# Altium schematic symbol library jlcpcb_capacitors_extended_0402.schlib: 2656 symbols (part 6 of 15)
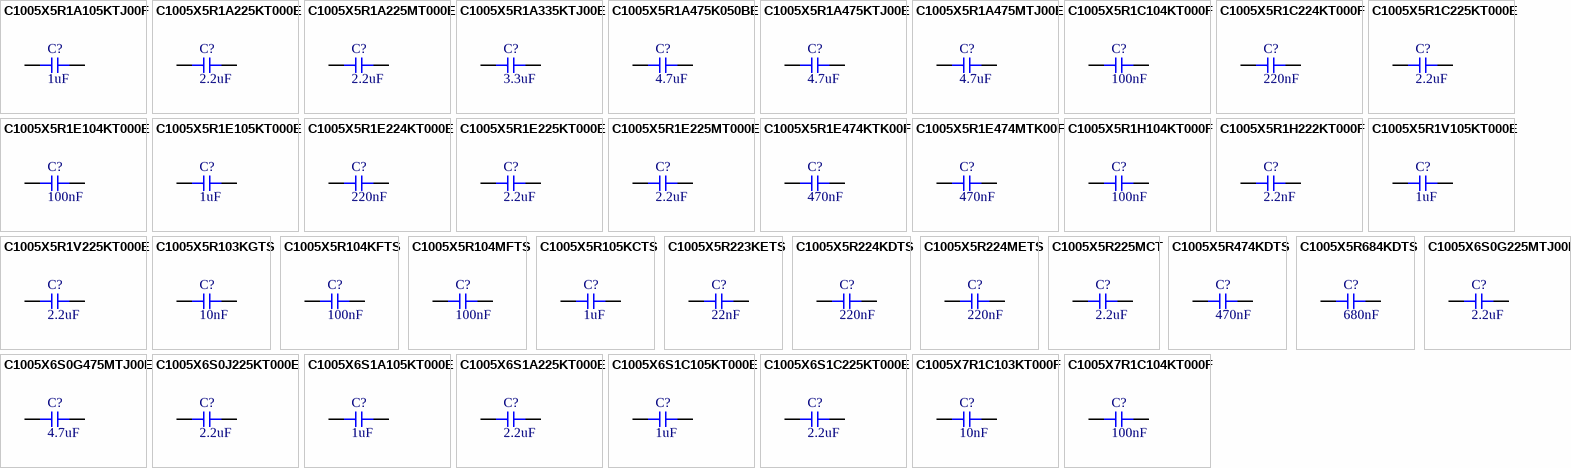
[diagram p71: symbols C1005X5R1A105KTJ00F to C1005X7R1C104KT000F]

## C1005X5R224KDTS
designator C?  Capacitance: 220nF  (hidden comment: *)
Capacitor, Ceramic (MLCC), 220nF, ±10%, 10V, X5R, ±10%, SMD 0402; Manufacturer: Darfon Elec; Manufacturer Part Number: C1005X5R224KDTS
footprint CAP-0402 (0402 (1005M) Capacitor)
pins: 1, 2

## C1005X5R224METS
designator C?  Capacitance: 220nF  (hidden comment: *)
Capacitor, Ceramic (MLCC), 220nF, ±20%, 16V, X5R, ±20%, SMD 0402; Manufacturer: Darfon Elec; Manufacturer Part Number: C1005X5R224METS
footprint CAP-0402 (0402 (1005M) Capacitor)
pins: 1, 2

## C1005X5R225MCT
designator C?  Capacitance: 2.2uF  (hidden comment: *)
Capacitor, Ceramic (MLCC), 2.2uF, ±20%, 6.3V, X5R, ±20%, SMD 0402; Manufacturer: Darfon Elec; Manufacturer Part Number: C1005X5R225MCT
footprint CAP-0402 (0402 (1005M) Capacitor)
pins: 1, 2

## C1005X5R474KDTS
designator C?  Capacitance: 470nF  (hidden comment: *)
Capacitor, Ceramic (MLCC), 470nF, ±10%, 10V, X5R, ±10%, SMD 0402; Manufacturer: Darfon Elec; Manufacturer Part Number: C1005X5R474KDTS
footprint CAP-0402 (0402 (1005M) Capacitor)
pins: 1, 2

## C1005X5R684KDTS
designator C?  Capacitance: 680nF  (hidden comment: *)
Capacitor, Ceramic (MLCC), 680nF, ±10%, 10V, X5R, ±10%, SMD 0402; Manufacturer: Darfon Elec; Manufacturer Part Number: C1005X5R684KDTS
footprint CAP-0402 (0402 (1005M) Capacitor)
pins: 1, 2

## C1005X6S0G225MTJ00F
designator C?  Capacitance: 2.2uF  (hidden comment: *)
Capacitor, Ceramic (MLCC), 2.2uF, ±20%, 4V, X6S, ±20%, SMD 0402; Manufacturer: TDK; Manufacturer Part Number: C1005X6S0G225MTJ00F
footprint CAP-0402 (0402 (1005M) Capacitor)
pins: 1, 2

## C1005X6S0G475MTJ00E
designator C?  Capacitance: 4.7uF  (hidden comment: *)
Capacitor, Ceramic (MLCC), 4.7uF, ±20%, 4V, X6S, ±20%, SMD 0402; Manufacturer: TDK; Manufacturer Part Number: C1005X6S0G475MTJ00E
footprint CAP-0402 (0402 (1005M) Capacitor)
pins: 1, 2

## C1005X6S0J225KT000E
designator C?  Capacitance: 2.2uF  (hidden comment: *)
Capacitor, Ceramic (MLCC), 2.2uF, ±10%, 6.3V, X6S, ±10%, SMD 0402; Manufacturer: TDK; Manufacturer Part Number: C1005X6S0J225KT000E
footprint CAP-0402 (0402 (1005M) Capacitor)
pins: 1, 2

## C1005X6S1A105KT000E
designator C?  Capacitance: 1uF  (hidden comment: *)
Capacitor, Ceramic (MLCC), 1uF, ±10%, 10V, X6S, ±10%, SMD 0402; Manufacturer: TDK; Manufacturer Part Number: C1005X6S1A105KT000E
footprint CAP-0402 (0402 (1005M) Capacitor)
pins: 1, 2

## C1005X6S1A225KT000E
designator C?  Capacitance: 2.2uF  (hidden comment: *)
Capacitor, Ceramic (MLCC), 2.2uF, ±10%, 10V, X6S, ±10%, SMD 0402; Manufacturer: TDK; Manufacturer Part Number: C1005X6S1A225KT000E
footprint CAP-0402 (0402 (1005M) Capacitor)
pins: 1, 2

## C1005X6S1C105KT000E
designator C?  Capacitance: 1uF  (hidden comment: *)
Capacitor, Ceramic (MLCC), 1uF, ±10%, 16V, X6S, ±10%, SMD 0402; Manufacturer: TDK; Manufacturer Part Number: C1005X6S1C105KT000E
footprint CAP-0402 (0402 (1005M) Capacitor)
pins: 1, 2

## C1005X6S1C225KT000E
designator C?  Capacitance: 2.2uF  (hidden comment: *)
Capacitor, Ceramic (MLCC), 2.2uF, ±10%, 16V, X6S, ±10%, SMD 0402; Manufacturer: TDK; Manufacturer Part Number: C1005X6S1C225KT000E
footprint CAP-0402 (0402 (1005M) Capacitor)
pins: 1, 2

## C1005X7R1C103KT000F
designator C?  Capacitance: 10nF  (hidden comment: *)
Capacitor, Ceramic (MLCC), 10nF, ±10%, 16V, X7R, ±10%, SMD 0402; Manufacturer: TDK; Manufacturer Part Number: C1005X7R1C103KT000F
footprint CAP-0402 (0402 (1005M) Capacitor)
pins: 1, 2

## C1005X7R1C104KT000F
designator C?  Capacitance: 100nF  (hidden comment: *)
Capacitor, Ceramic (MLCC), 100nF, ±10%, 16V, X7R, ±10%, SMD 0402; Manufacturer: TDK; Manufacturer Part Number: C1005X7R1C104KT000F
footprint CAP-0402 (0402 (1005M) Capacitor)
pins: 1, 2

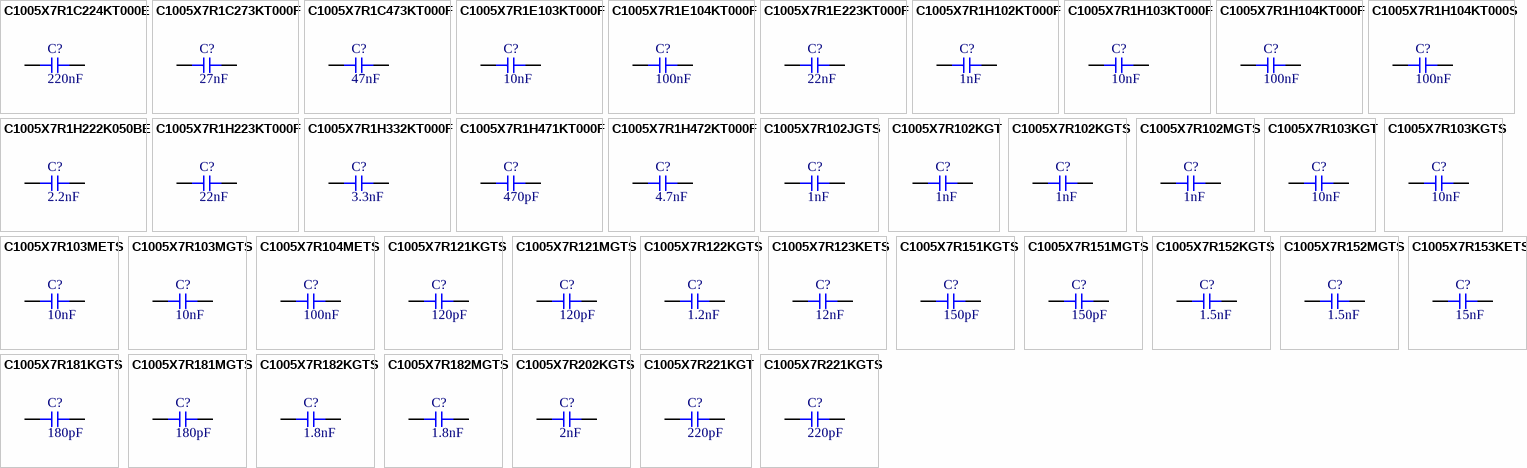
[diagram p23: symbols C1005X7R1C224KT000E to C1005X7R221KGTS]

## C1005X7R1C224KT000E
designator C?  Capacitance: 220nF  (hidden comment: *)
Capacitor, Ceramic (MLCC), 220nF, ±10%, 16V, X7R, ±10%, SMD 0402; Manufacturer: TDK; Manufacturer Part Number: C1005X7R1C224KT000E
footprint CAP-0402 (0402 (1005M) Capacitor)
pins: 1, 2

## C1005X7R1C273KT000F
designator C?  Capacitance: 27nF  (hidden comment: *)
Capacitor, Ceramic (MLCC), 27nF, ±10%, 16V, X7R, ±10%, SMD 0402; Manufacturer: TDK; Manufacturer Part Number: C1005X7R1C273KT000F
footprint CAP-0402 (0402 (1005M) Capacitor)
pins: 1, 2

## C1005X7R1C473KT000F
designator C?  Capacitance: 47nF  (hidden comment: *)
Capacitor, Ceramic (MLCC), 47nF, ±10%, 16V, X7R, ±10%, SMD 0402; Manufacturer: TDK; Manufacturer Part Number: C1005X7R1C473KT000F
footprint CAP-0402 (0402 (1005M) Capacitor)
pins: 1, 2

## C1005X7R1E103KT000F
designator C?  Capacitance: 10nF  (hidden comment: *)
Capacitor, Ceramic (MLCC), 10nF, ±10%, 25V, X7R, ±10%, SMD 0402; Manufacturer: TDK; Manufacturer Part Number: C1005X7R1E103KT000F
footprint CAP-0402 (0402 (1005M) Capacitor)
pins: 1, 2

## C1005X7R1E104KT000F
designator C?  Capacitance: 100nF  (hidden comment: *)
Capacitor, Ceramic (MLCC), 100nF, ±10%, 25V, X7R, ±10%, SMD 0402; Manufacturer: TDK; Manufacturer Part Number: C1005X7R1E104KT000F
footprint CAP-0402 (0402 (1005M) Capacitor)
pins: 1, 2

## C1005X7R1E223KT000F
designator C?  Capacitance: 22nF  (hidden comment: *)
Capacitor, Ceramic (MLCC), 22nF, ±10%, 25V, X7R, ±10%, SMD 0402; Manufacturer: TDK; Manufacturer Part Number: C1005X7R1E223KT000F
footprint CAP-0402 (0402 (1005M) Capacitor)
pins: 1, 2

## C1005X7R1H102KT000F
designator C?  Capacitance: 1nF  (hidden comment: *)
Capacitor, Ceramic (MLCC), 1nF, ±10%, 50V, X7R, ±10%, SMD 0402; Manufacturer: TDK; Manufacturer Part Number: C1005X7R1H102KT000F
footprint CAP-0402 (0402 (1005M) Capacitor)
pins: 1, 2

## C1005X7R1H103KT000F
designator C?  Capacitance: 10nF  (hidden comment: *)
Capacitor, Ceramic (MLCC), 10nF, ±10%, 50V, X7R, ±10%, SMD 0402; Manufacturer: TDK; Manufacturer Part Number: C1005X7R1H103KT000F
footprint CAP-0402 (0402 (1005M) Capacitor)
pins: 1, 2

## C1005X7R1H104KT000F
designator C?  Capacitance: 100nF  (hidden comment: *)
Capacitor, Ceramic (MLCC), 100nF, ±10%, 50V, X7R, ±10%, SMD 0402; Manufacturer: TDK; Manufacturer Part Number: C1005X7R1H104KT000F
footprint CAP-0402 (0402 (1005M) Capacitor)
pins: 1, 2

## C1005X7R1H104KT000S
designator C?  Capacitance: 100nF  (hidden comment: *)
Capacitor, Ceramic (MLCC), 100nF, ±10%, 50V, X7R, ±10%, SMD 0402; Manufacturer: TDK; Manufacturer Part Number: C1005X7R1H104KT000S
footprint CAP-0402 (0402 (1005M) Capacitor)
pins: 1, 2

## C1005X7R1H222K050BE
designator C?  Capacitance: 2.2nF  (hidden comment: *)
Capacitor, Ceramic (MLCC), 2.2nF, ±10%, 50V, X7R, ±10%, SMD 0402; Manufacturer: TDK; Manufacturer Part Number: C1005X7R1H222K050BE
footprint CAP-0402 (0402 (1005M) Capacitor)
pins: 1, 2

## C1005X7R1H223KT000F
designator C?  Capacitance: 22nF  (hidden comment: *)
Capacitor, Ceramic (MLCC), 22nF, ±10%, 50V, X7R, ±10%, SMD 0402; Manufacturer: TDK; Manufacturer Part Number: C1005X7R1H223KT000F
footprint CAP-0402 (0402 (1005M) Capacitor)
pins: 1, 2

## C1005X7R1H332KT000F
designator C?  Capacitance: 3.3nF  (hidden comment: *)
Capacitor, Ceramic (MLCC), 3.3nF, ±10%, 50V, X7R, ±10%, SMD 0402; Manufacturer: TDK; Manufacturer Part Number: C1005X7R1H332KT000F
footprint CAP-0402 (0402 (1005M) Capacitor)
pins: 1, 2

## C1005X7R1H471KT000F
designator C?  Capacitance: 470pF  (hidden comment: *)
Capacitor, Ceramic (MLCC), 470pF, ±10%, 50V, X7R, ±10%, SMD 0402; Manufacturer: TDK; Manufacturer Part Number: C1005X7R1H471KT000F
footprint CAP-0402 (0402 (1005M) Capacitor)
pins: 1, 2

## C1005X7R1H472KT000F
designator C?  Capacitance: 4.7nF  (hidden comment: *)
Capacitor, Ceramic (MLCC), 4.7nF, ±10%, 50V, X7R, ±10%, SMD 0402; Manufacturer: TDK; Manufacturer Part Number: C1005X7R1H472KT000F
footprint CAP-0402 (0402 (1005M) Capacitor)
pins: 1, 2

## C1005X7R102JGTS
designator C?  Capacitance: 1nF  (hidden comment: *)
Capacitor, Ceramic (MLCC), 1nF, ±5%, 50V, X7R, ±5%, SMD 0402; Manufacturer: Darfon Elec; Manufacturer Part Number: C1005X7R102JGTS
footprint CAP-0402 (0402 (1005M) Capacitor)
pins: 1, 2

## C1005X7R102KGT
designator C?  Capacitance: 1nF  (hidden comment: *)
Capacitor, Ceramic (MLCC), 1nF, ±10%, 50V, X7R, ±10%, SMD 0402; Manufacturer: Darfon Elec; Manufacturer Part Number: C1005X7R102KGT
footprint CAP-0402 (0402 (1005M) Capacitor)
pins: 1, 2

## C1005X7R102KGTS
designator C?  Capacitance: 1nF  (hidden comment: *)
Capacitor, Ceramic (MLCC), 1nF, ±10%, 50V, X7R, ±10%, SMD 0402; Manufacturer: Darfon Elec; Manufacturer Part Number: C1005X7R102KGTS
footprint CAP-0402 (0402 (1005M) Capacitor)
pins: 1, 2

## C1005X7R102MGTS
designator C?  Capacitance: 1nF  (hidden comment: *)
Capacitor, Ceramic (MLCC), 1nF, ±20%, 50V, X7R, ±20%, SMD 0402; Manufacturer: Darfon Elec; Manufacturer Part Number: C1005X7R102MGTS
footprint CAP-0402 (0402 (1005M) Capacitor)
pins: 1, 2

## C1005X7R103KGT
designator C?  Capacitance: 10nF  (hidden comment: *)
Capacitor, Ceramic (MLCC), 10nF, ±10%, 50V, X7R, ±10%, SMD 0402; Manufacturer: Darfon Elec; Manufacturer Part Number: C1005X7R103KGT
footprint CAP-0402 (0402 (1005M) Capacitor)
pins: 1, 2

## C1005X7R103KGTS
designator C?  Capacitance: 10nF  (hidden comment: *)
Capacitor, Ceramic (MLCC), 10nF, ±10%, 50V, X7R, ±10%, SMD 0402; Manufacturer: Darfon Elec; Manufacturer Part Number: C1005X7R103KGTS
footprint CAP-0402 (0402 (1005M) Capacitor)
pins: 1, 2

## C1005X7R103METS
designator C?  Capacitance: 10nF  (hidden comment: *)
Capacitor, Ceramic (MLCC), 10nF, ±20%, 16V, X7R, ±20%, SMD 0402; Manufacturer: Darfon Elec; Manufacturer Part Number: C1005X7R103METS
footprint CAP-0402 (0402 (1005M) Capacitor)
pins: 1, 2

## C1005X7R103MGTS
designator C?  Capacitance: 10nF  (hidden comment: *)
Capacitor, Ceramic (MLCC), 10nF, ±20%, 50V, X7R, ±20%, SMD 0402; Manufacturer: Darfon Elec; Manufacturer Part Number: C1005X7R103MGTS
footprint CAP-0402 (0402 (1005M) Capacitor)
pins: 1, 2

## C1005X7R104METS
designator C?  Capacitance: 100nF  (hidden comment: *)
Capacitor, Ceramic (MLCC), 100nF, ±20%, 16V, X7R, ±20%, SMD 0402; Manufacturer: Darfon Elec; Manufacturer Part Number: C1005X7R104METS
footprint CAP-0402 (0402 (1005M) Capacitor)
pins: 1, 2

## C1005X7R121KGTS
designator C?  Capacitance: 120pF  (hidden comment: *)
Capacitor, Ceramic (MLCC), 120pF, ±10%, 50V, X7R, ±10%, SMD 0402; Manufacturer: Darfon Elec; Manufacturer Part Number: C1005X7R121KGTS
footprint CAP-0402 (0402 (1005M) Capacitor)
pins: 1, 2

## C1005X7R121MGTS
designator C?  Capacitance: 120pF  (hidden comment: *)
Capacitor, Ceramic (MLCC), 120pF, ±20%, 50V, X7R, ±20%, SMD 0402; Manufacturer: Darfon Elec; Manufacturer Part Number: C1005X7R121MGTS
footprint CAP-0402 (0402 (1005M) Capacitor)
pins: 1, 2

## C1005X7R122KGTS
designator C?  Capacitance: 1.2nF  (hidden comment: *)
Capacitor, Ceramic (MLCC), 1.2nF, ±10%, 50V, X7R, ±10%, SMD 0402; Manufacturer: Darfon Elec; Manufacturer Part Number: C1005X7R122KGTS
footprint CAP-0402 (0402 (1005M) Capacitor)
pins: 1, 2

## C1005X7R123KETS
designator C?  Capacitance: 12nF  (hidden comment: *)
Capacitor, Ceramic (MLCC), 12nF, ±10%, 16V, X7R, ±10%, SMD 0402; Manufacturer: Darfon Elec; Manufacturer Part Number: C1005X7R123KETS
footprint CAP-0402 (0402 (1005M) Capacitor)
pins: 1, 2

## C1005X7R151KGTS
designator C?  Capacitance: 150pF  (hidden comment: *)
Capacitor, Ceramic (MLCC), 150pF, ±10%, 50V, X7R, ±10%, SMD 0402; Manufacturer: Darfon Elec; Manufacturer Part Number: C1005X7R151KGTS
footprint CAP-0402 (0402 (1005M) Capacitor)
pins: 1, 2

## C1005X7R151MGTS
designator C?  Capacitance: 150pF  (hidden comment: *)
Capacitor, Ceramic (MLCC), 150pF, ±20%, 50V, X7R, ±20%, SMD 0402; Manufacturer: Darfon Elec; Manufacturer Part Number: C1005X7R151MGTS
footprint CAP-0402 (0402 (1005M) Capacitor)
pins: 1, 2

## C1005X7R152KGTS
designator C?  Capacitance: 1.5nF  (hidden comment: *)
Capacitor, Ceramic (MLCC), 1.5nF, ±10%, 50V, X7R, ±10%, SMD 0402; Manufacturer: Darfon Elec; Manufacturer Part Number: C1005X7R152KGTS
footprint CAP-0402 (0402 (1005M) Capacitor)
pins: 1, 2

## C1005X7R152MGTS
designator C?  Capacitance: 1.5nF  (hidden comment: *)
Capacitor, Ceramic (MLCC), 1.5nF, ±20%, 50V, X7R, ±20%, SMD 0402; Manufacturer: Darfon Elec; Manufacturer Part Number: C1005X7R152MGTS
footprint CAP-0402 (0402 (1005M) Capacitor)
pins: 1, 2

## C1005X7R153KETS
designator C?  Capacitance: 15nF  (hidden comment: *)
Capacitor, Ceramic (MLCC), 15nF, ±10%, 16V, X7R, ±10%, SMD 0402; Manufacturer: Darfon Elec; Manufacturer Part Number: C1005X7R153KETS
footprint CAP-0402 (0402 (1005M) Capacitor)
pins: 1, 2

## C1005X7R181KGTS
designator C?  Capacitance: 180pF  (hidden comment: *)
Capacitor, Ceramic (MLCC), 180pF, ±10%, 50V, X7R, ±10%, SMD 0402; Manufacturer: Darfon Elec; Manufacturer Part Number: C1005X7R181KGTS
footprint CAP-0402 (0402 (1005M) Capacitor)
pins: 1, 2

## C1005X7R181MGTS
designator C?  Capacitance: 180pF  (hidden comment: *)
Capacitor, Ceramic (MLCC), 180pF, ±20%, 50V, X7R, ±20%, SMD 0402; Manufacturer: Darfon Elec; Manufacturer Part Number: C1005X7R181MGTS
footprint CAP-0402 (0402 (1005M) Capacitor)
pins: 1, 2

## C1005X7R182KGTS
designator C?  Capacitance: 1.8nF  (hidden comment: *)
Capacitor, Ceramic (MLCC), 1.8nF, ±10%, 50V, X7R, ±10%, SMD 0402; Manufacturer: Darfon Elec; Manufacturer Part Number: C1005X7R182KGTS
footprint CAP-0402 (0402 (1005M) Capacitor)
pins: 1, 2

## C1005X7R182MGTS
designator C?  Capacitance: 1.8nF  (hidden comment: *)
Capacitor, Ceramic (MLCC), 1.8nF, ±20%, 50V, X7R, ±20%, SMD 0402; Manufacturer: Darfon Elec; Manufacturer Part Number: C1005X7R182MGTS
footprint CAP-0402 (0402 (1005M) Capacitor)
pins: 1, 2

## C1005X7R202KGTS
designator C?  Capacitance: 2nF  (hidden comment: *)
Capacitor, Ceramic (MLCC), 2nF, ±10%, 50V, X7R, ±10%, SMD 0402; Manufacturer: Darfon Elec; Manufacturer Part Number: C1005X7R202KGTS
footprint CAP-0402 (0402 (1005M) Capacitor)
pins: 1, 2

## C1005X7R221KGT
designator C?  Capacitance: 220pF  (hidden comment: *)
Capacitor, Ceramic (MLCC), 220pF, ±10%, 50V, X7R, ±10%, SMD 0402; Manufacturer: Darfon Elec; Manufacturer Part Number: C1005X7R221KGT
footprint CAP-0402 (0402 (1005M) Capacitor)
pins: 1, 2

## C1005X7R221KGTS
designator C?  Capacitance: 220pF  (hidden comment: *)
Capacitor, Ceramic (MLCC), 220pF, ±10%, 50V, X7R, ±10%, SMD 0402; Manufacturer: Darfon Elec; Manufacturer Part Number: C1005X7R221KGTS
footprint CAP-0402 (0402 (1005M) Capacitor)
pins: 1, 2

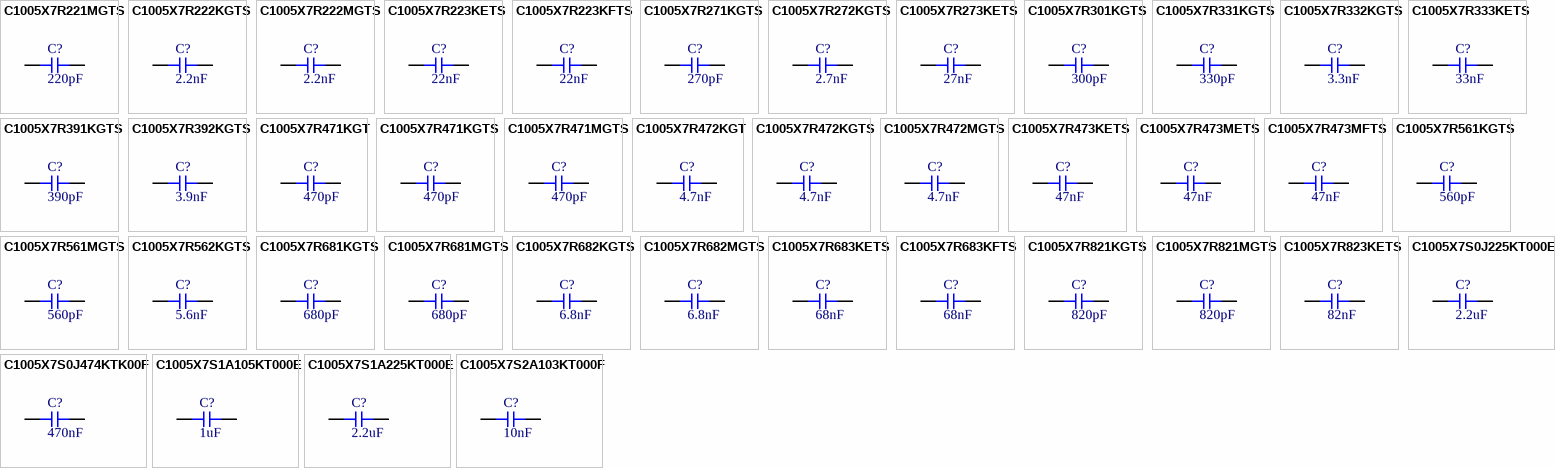
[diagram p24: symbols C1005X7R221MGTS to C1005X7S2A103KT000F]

## C1005X7R221MGTS
designator C?  Capacitance: 220pF  (hidden comment: *)
Capacitor, Ceramic (MLCC), 220pF, ±20%, 50V, X7R, ±20%, SMD 0402; Manufacturer: Darfon Elec; Manufacturer Part Number: C1005X7R221MGTS
footprint CAP-0402 (0402 (1005M) Capacitor)
pins: 1, 2

## C1005X7R222KGTS
designator C?  Capacitance: 2.2nF  (hidden comment: *)
Capacitor, Ceramic (MLCC), 2.2nF, ±10%, 50V, X7R, ±10%, SMD 0402; Manufacturer: Darfon Elec; Manufacturer Part Number: C1005X7R222KGTS
footprint CAP-0402 (0402 (1005M) Capacitor)
pins: 1, 2

## C1005X7R222MGTS
designator C?  Capacitance: 2.2nF  (hidden comment: *)
Capacitor, Ceramic (MLCC), 2.2nF, ±20%, 50V, X7R, ±20%, SMD 0402; Manufacturer: Darfon Elec; Manufacturer Part Number: C1005X7R222MGTS
footprint CAP-0402 (0402 (1005M) Capacitor)
pins: 1, 2

## C1005X7R223KETS
designator C?  Capacitance: 22nF  (hidden comment: *)
Capacitor, Ceramic (MLCC), 22nF, ±10%, 16V, X7R, ±10%, SMD 0402; Manufacturer: Darfon Elec; Manufacturer Part Number: C1005X7R223KETS
footprint CAP-0402 (0402 (1005M) Capacitor)
pins: 1, 2

## C1005X7R223KFTS
designator C?  Capacitance: 22nF  (hidden comment: *)
Capacitor, Ceramic (MLCC), 22nF, ±10%, 25V, X7R, ±10%, SMD 0402; Manufacturer: Darfon Elec; Manufacturer Part Number: C1005X7R223KFTS
footprint CAP-0402 (0402 (1005M) Capacitor)
pins: 1, 2

## C1005X7R271KGTS
designator C?  Capacitance: 270pF  (hidden comment: *)
Capacitor, Ceramic (MLCC), 270pF, ±10%, 50V, X7R, ±10%, SMD 0402; Manufacturer: Darfon Elec; Manufacturer Part Number: C1005X7R271KGTS
footprint CAP-0402 (0402 (1005M) Capacitor)
pins: 1, 2

## C1005X7R272KGTS
designator C?  Capacitance: 2.7nF  (hidden comment: *)
Capacitor, Ceramic (MLCC), 2.7nF, ±10%, 50V, X7R, ±10%, SMD 0402; Manufacturer: Darfon Elec; Manufacturer Part Number: C1005X7R272KGTS
footprint CAP-0402 (0402 (1005M) Capacitor)
pins: 1, 2

## C1005X7R273KETS
designator C?  Capacitance: 27nF  (hidden comment: *)
Capacitor, Ceramic (MLCC), 27nF, ±10%, 16V, X7R, ±10%, SMD 0402; Manufacturer: Darfon Elec; Manufacturer Part Number: C1005X7R273KETS
footprint CAP-0402 (0402 (1005M) Capacitor)
pins: 1, 2

## C1005X7R301KGTS
designator C?  Capacitance: 300pF  (hidden comment: *)
Capacitor, Ceramic (MLCC), 300pF, ±10%, 50V, X7R, ±10%, SMD 0402; Manufacturer: Darfon Elec; Manufacturer Part Number: C1005X7R301KGTS
footprint CAP-0402 (0402 (1005M) Capacitor)
pins: 1, 2

## C1005X7R331KGTS
designator C?  Capacitance: 330pF  (hidden comment: *)
Capacitor, Ceramic (MLCC), 330pF, ±10%, 50V, X7R, ±10%, SMD 0402; Manufacturer: Darfon Elec; Manufacturer Part Number: C1005X7R331KGTS
footprint CAP-0402 (0402 (1005M) Capacitor)
pins: 1, 2

## C1005X7R332KGTS
designator C?  Capacitance: 3.3nF  (hidden comment: *)
Capacitor, Ceramic (MLCC), 3.3nF, ±10%, 50V, X7R, ±10%, SMD 0402; Manufacturer: Darfon Elec; Manufacturer Part Number: C1005X7R332KGTS
footprint CAP-0402 (0402 (1005M) Capacitor)
pins: 1, 2

## C1005X7R333KETS
designator C?  Capacitance: 33nF  (hidden comment: *)
Capacitor, Ceramic (MLCC), 33nF, ±10%, 16V, X7R, ±10%, SMD 0402; Manufacturer: Darfon Elec; Manufacturer Part Number: C1005X7R333KETS
footprint CAP-0402 (0402 (1005M) Capacitor)
pins: 1, 2

## C1005X7R391KGTS
designator C?  Capacitance: 390pF  (hidden comment: *)
Capacitor, Ceramic (MLCC), 390pF, ±10%, 50V, X7R, ±10%, SMD 0402; Manufacturer: Darfon Elec; Manufacturer Part Number: C1005X7R391KGTS
footprint CAP-0402 (0402 (1005M) Capacitor)
pins: 1, 2

## C1005X7R392KGTS
designator C?  Capacitance: 3.9nF  (hidden comment: *)
Capacitor, Ceramic (MLCC), 3.9nF, ±10%, 50V, X7R, ±10%, SMD 0402; Manufacturer: Darfon Elec; Manufacturer Part Number: C1005X7R392KGTS
footprint CAP-0402 (0402 (1005M) Capacitor)
pins: 1, 2

## C1005X7R471KGT
designator C?  Capacitance: 470pF  (hidden comment: *)
Capacitor, Ceramic (MLCC), 470pF, ±10%, 50V, X7R, ±10%, SMD 0402; Manufacturer: Darfon Elec; Manufacturer Part Number: C1005X7R471KGT
footprint CAP-0402 (0402 (1005M) Capacitor)
pins: 1, 2

## C1005X7R471KGTS
designator C?  Capacitance: 470pF  (hidden comment: *)
Capacitor, Ceramic (MLCC), 470pF, ±10%, 50V, X7R, ±10%, SMD 0402; Manufacturer: Darfon Elec; Manufacturer Part Number: C1005X7R471KGTS
footprint CAP-0402 (0402 (1005M) Capacitor)
pins: 1, 2

## C1005X7R471MGTS
designator C?  Capacitance: 470pF  (hidden comment: *)
Capacitor, Ceramic (MLCC), 470pF, ±20%, 50V, X7R, ±20%, SMD 0402; Manufacturer: Darfon Elec; Manufacturer Part Number: C1005X7R471MGTS
footprint CAP-0402 (0402 (1005M) Capacitor)
pins: 1, 2

## C1005X7R472KGT
designator C?  Capacitance: 4.7nF  (hidden comment: *)
Capacitor, Ceramic (MLCC), 4.7nF, ±10%, 50V, X7R, ±10%, SMD 0402; Manufacturer: Darfon Elec; Manufacturer Part Number: C1005X7R472KGT
footprint CAP-0402 (0402 (1005M) Capacitor)
pins: 1, 2

## C1005X7R472KGTS
designator C?  Capacitance: 4.7nF  (hidden comment: *)
Capacitor, Ceramic (MLCC), 4.7nF, ±10%, 50V, X7R, ±10%, SMD 0402; Manufacturer: Darfon Elec; Manufacturer Part Number: C1005X7R472KGTS
footprint CAP-0402 (0402 (1005M) Capacitor)
pins: 1, 2

## C1005X7R472MGTS
designator C?  Capacitance: 4.7nF  (hidden comment: *)
Capacitor, Ceramic (MLCC), 4.7nF, ±20%, 50V, X7R, ±20%, SMD 0402; Manufacturer: Darfon Elec; Manufacturer Part Number: C1005X7R472MGTS
footprint CAP-0402 (0402 (1005M) Capacitor)
pins: 1, 2

## C1005X7R473KETS
designator C?  Capacitance: 47nF  (hidden comment: *)
Capacitor, Ceramic (MLCC), 47nF, ±10%, 16V, X7R, ±10%, SMD 0402; Manufacturer: Darfon Elec; Manufacturer Part Number: C1005X7R473KETS
footprint CAP-0402 (0402 (1005M) Capacitor)
pins: 1, 2

## C1005X7R473METS
designator C?  Capacitance: 47nF  (hidden comment: *)
Capacitor, Ceramic (MLCC), 47nF, ±20%, 16V, X7R, ±20%, SMD 0402; Manufacturer: Darfon Elec; Manufacturer Part Number: C1005X7R473METS
footprint CAP-0402 (0402 (1005M) Capacitor)
pins: 1, 2

## C1005X7R473MFTS
designator C?  Capacitance: 47nF  (hidden comment: *)
Capacitor, Ceramic (MLCC), 47nF, ±20%, 25V, X7R, ±20%, SMD 0402; Manufacturer: Darfon Elec; Manufacturer Part Number: C1005X7R473MFTS
footprint CAP-0402 (0402 (1005M) Capacitor)
pins: 1, 2

## C1005X7R561KGTS
designator C?  Capacitance: 560pF  (hidden comment: *)
Capacitor, Ceramic (MLCC), 560pF, ±10%, 50V, X7R, ±10%, SMD 0402; Manufacturer: Darfon Elec; Manufacturer Part Number: C1005X7R561KGTS
footprint CAP-0402 (0402 (1005M) Capacitor)
pins: 1, 2

## C1005X7R561MGTS
designator C?  Capacitance: 560pF  (hidden comment: *)
Capacitor, Ceramic (MLCC), 560pF, ±20%, 50V, X7R, ±20%, SMD 0402; Manufacturer: Darfon Elec; Manufacturer Part Number: C1005X7R561MGTS
footprint CAP-0402 (0402 (1005M) Capacitor)
pins: 1, 2

## C1005X7R562KGTS
designator C?  Capacitance: 5.6nF  (hidden comment: *)
Capacitor, Ceramic (MLCC), 5.6nF, ±10%, 50V, X7R, ±10%, SMD 0402; Manufacturer: Darfon Elec; Manufacturer Part Number: C1005X7R562KGTS
footprint CAP-0402 (0402 (1005M) Capacitor)
pins: 1, 2

## C1005X7R681KGTS
designator C?  Capacitance: 680pF  (hidden comment: *)
Capacitor, Ceramic (MLCC), 680pF, ±10%, 50V, X7R, ±10%, SMD 0402; Manufacturer: Darfon Elec; Manufacturer Part Number: C1005X7R681KGTS
footprint CAP-0402 (0402 (1005M) Capacitor)
pins: 1, 2

## C1005X7R681MGTS
designator C?  Capacitance: 680pF  (hidden comment: *)
Capacitor, Ceramic (MLCC), 680pF, ±20%, 50V, X7R, ±20%, SMD 0402; Manufacturer: Darfon Elec; Manufacturer Part Number: C1005X7R681MGTS
footprint CAP-0402 (0402 (1005M) Capacitor)
pins: 1, 2

## C1005X7R682KGTS
designator C?  Capacitance: 6.8nF  (hidden comment: *)
Capacitor, Ceramic (MLCC), 6.8nF, ±10%, 50V, X7R, ±10%, SMD 0402; Manufacturer: Darfon Elec; Manufacturer Part Number: C1005X7R682KGTS
footprint CAP-0402 (0402 (1005M) Capacitor)
pins: 1, 2

## C1005X7R682MGTS
designator C?  Capacitance: 6.8nF  (hidden comment: *)
Capacitor, Ceramic (MLCC), 6.8nF, ±20%, 50V, X7R, ±20%, SMD 0402; Manufacturer: Darfon Elec; Manufacturer Part Number: C1005X7R682MGTS
footprint CAP-0402 (0402 (1005M) Capacitor)
pins: 1, 2

## C1005X7R683KETS
designator C?  Capacitance: 68nF  (hidden comment: *)
Capacitor, Ceramic (MLCC), 68nF, ±10%, 16V, X7R, ±10%, SMD 0402; Manufacturer: Darfon Elec; Manufacturer Part Number: C1005X7R683KETS
footprint CAP-0402 (0402 (1005M) Capacitor)
pins: 1, 2

## C1005X7R683KFTS
designator C?  Capacitance: 68nF  (hidden comment: *)
Capacitor, Ceramic (MLCC), 68nF, ±10%, 25V, X7R, ±10%, SMD 0402; Manufacturer: Darfon Elec; Manufacturer Part Number: C1005X7R683KFTS
footprint CAP-0402 (0402 (1005M) Capacitor)
pins: 1, 2

## C1005X7R821KGTS
designator C?  Capacitance: 820pF  (hidden comment: *)
Capacitor, Ceramic (MLCC), 820pF, ±10%, 50V, X7R, ±10%, SMD 0402; Manufacturer: Darfon Elec; Manufacturer Part Number: C1005X7R821KGTS
footprint CAP-0402 (0402 (1005M) Capacitor)
pins: 1, 2

## C1005X7R821MGTS
designator C?  Capacitance: 820pF  (hidden comment: *)
Capacitor, Ceramic (MLCC), 820pF, ±20%, 50V, X7R, ±20%, SMD 0402; Manufacturer: Darfon Elec; Manufacturer Part Number: C1005X7R821MGTS
footprint CAP-0402 (0402 (1005M) Capacitor)
pins: 1, 2

## C1005X7R823KETS
designator C?  Capacitance: 82nF  (hidden comment: *)
Capacitor, Ceramic (MLCC), 82nF, ±10%, 16V, X7R, ±10%, SMD 0402; Manufacturer: Darfon Elec; Manufacturer Part Number: C1005X7R823KETS
footprint CAP-0402 (0402 (1005M) Capacitor)
pins: 1, 2

## C1005X7S0J225KT000E
designator C?  Capacitance: 2.2uF  (hidden comment: *)
Capacitor, Ceramic (MLCC), 2.2uF, ±10%, 6.3V, X7S, ±10%, SMD 0402; Manufacturer: TDK; Manufacturer Part Number: C1005X7S0J225KT000E
footprint CAP-0402 (0402 (1005M) Capacitor)
pins: 1, 2

## C1005X7S0J474KTK00F
designator C?  Capacitance: 470nF  (hidden comment: *)
Capacitor, Ceramic (MLCC), 470nF, ±10%, 6.3V, X7S, ±10%, SMD 0402; Manufacturer: TDK; Manufacturer Part Number: C1005X7S0J474KTK00F
footprint CAP-0402 (0402 (1005M) Capacitor)
pins: 1, 2

## C1005X7S1A105KT000E
designator C?  Capacitance: 1uF  (hidden comment: *)
Capacitor, Ceramic (MLCC), 1uF, ±10%, 10V, X7S, ±10%, SMD 0402; Manufacturer: TDK; Manufacturer Part Number: C1005X7S1A105KT000E
footprint CAP-0402 (0402 (1005M) Capacitor)
pins: 1, 2

## C1005X7S1A225KT000E
designator C?  Capacitance: 2.2uF  (hidden comment: *)
Capacitor, Ceramic (MLCC), 2.2uF, ±10%, 10V, X7S, ±10%, SMD 0402; Manufacturer: TDK; Manufacturer Part Number: C1005X7S1A225KT000E
footprint CAP-0402 (0402 (1005M) Capacitor)
pins: 1, 2

## C1005X7S2A103KT000F
designator C?  Capacitance: 10nF  (hidden comment: *)
Capacitor, Ceramic (MLCC), 10nF, ±10%, 100V, X7S, ±10%, SMD 0402; Manufacturer: TDK; Manufacturer Part Number: C1005X7S2A103KT000F
footprint CAP-0402 (0402 (1005M) Capacitor)
pins: 1, 2

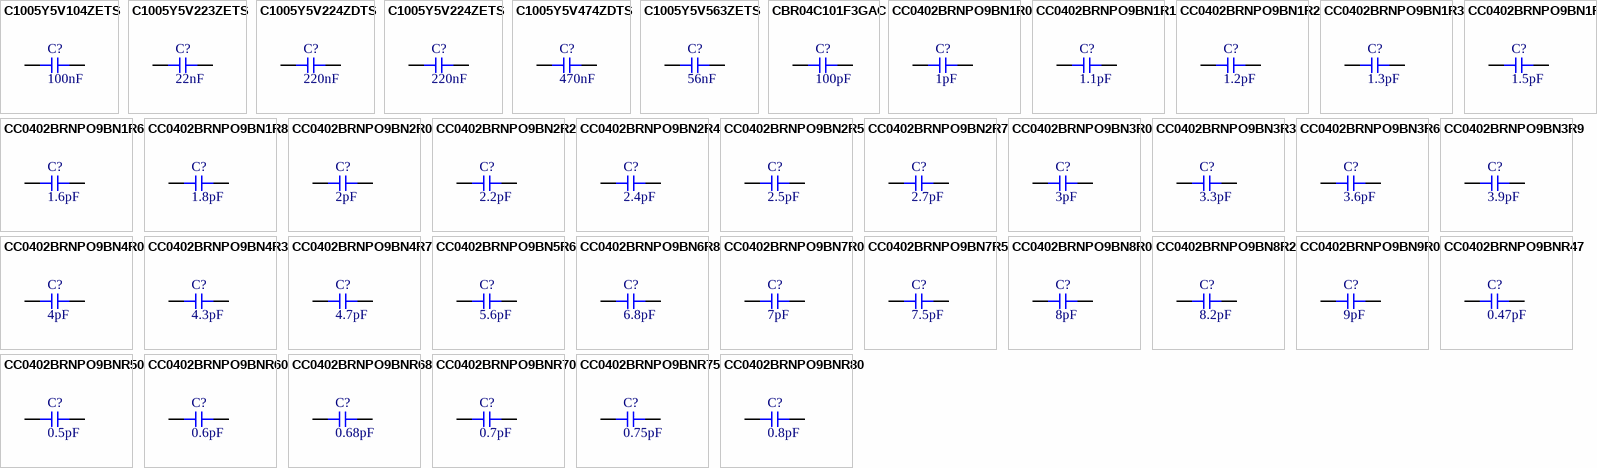
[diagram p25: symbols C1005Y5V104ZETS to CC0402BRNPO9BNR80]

## C1005Y5V104ZETS
designator C?  Capacitance: 100nF  (hidden comment: *)
Capacitor, Ceramic (MLCC), 100nF, 16V, Y5V, SMD 0402; Manufacturer: Darfon Elec; Manufacturer Part Number: C1005Y5V104ZETS; Temperature Rating: -20%~+80%
footprint CAP-0402 (0402 (1005M) Capacitor)
pins: 1, 2

## C1005Y5V223ZETS
designator C?  Capacitance: 22nF  (hidden comment: *)
Capacitor, Ceramic (MLCC), 22nF, 16V, Y5V, SMD 0402; Manufacturer: Darfon Elec; Manufacturer Part Number: C1005Y5V223ZETS; Temperature Rating: -20%~+80%
footprint CAP-0402 (0402 (1005M) Capacitor)
pins: 1, 2

## C1005Y5V224ZDTS
designator C?  Capacitance: 220nF  (hidden comment: *)
Capacitor, Ceramic (MLCC), 220nF, 10V, Y5V, SMD 0402; Manufacturer: Darfon Elec; Manufacturer Part Number: C1005Y5V224ZDTS; Temperature Rating: -20%~+80%
footprint CAP-0402 (0402 (1005M) Capacitor)
pins: 1, 2

## C1005Y5V224ZETS
designator C?  Capacitance: 220nF  (hidden comment: *)
Capacitor, Ceramic (MLCC), 220nF, 16V, Y5V, SMD 0402; Manufacturer: Darfon Elec; Manufacturer Part Number: C1005Y5V224ZETS; Temperature Rating: -20%~+80%
footprint CAP-0402 (0402 (1005M) Capacitor)
pins: 1, 2

## C1005Y5V474ZDTS
designator C?  Capacitance: 470nF  (hidden comment: *)
Capacitor, Ceramic (MLCC), 470nF, 10V, Y5V, SMD 0402; Manufacturer: Darfon Elec; Manufacturer Part Number: C1005Y5V474ZDTS; Temperature Rating: -20%~+80%
footprint CAP-0402 (0402 (1005M) Capacitor)
pins: 1, 2

## C1005Y5V563ZETS
designator C?  Capacitance: 56nF  (hidden comment: *)
Capacitor, Ceramic (MLCC), 56nF, 16V, Y5V, SMD 0402; Manufacturer: Darfon Elec; Manufacturer Part Number: C1005Y5V563ZETS; Temperature Rating: -20%~+80%
footprint CAP-0402 (0402 (1005M) Capacitor)
pins: 1, 2

## CBR04C101F3GAC
designator C?  Capacitance: 100pF  (hidden comment: *)
Capacitor, Ceramic (MLCC), 100pF, ±1%, 25V, ±1%, SMD 0402; Manufacturer: KEMET; Manufacturer Part Number: CBR04C101F3GAC
footprint CAP-0402 (0402 (1005M) Capacitor)
pins: 1, 2

## CC0402BRNPO9BN1R0
designator C?  Capacitance: 1pF  (hidden comment: *)
Capacitor, Ceramic (MLCC), 1pF, ±0.1pF, 50V, NP0, ±0.1pF, SMD 0402; Manufacturer: YAGEO; Manufacturer Part Number: CC0402BRNPO9BN1R0
footprint CAP-0402 (0402 (1005M) Capacitor)
pins: 1, 2

## CC0402BRNPO9BN1R1
designator C?  Capacitance: 1.1pF  (hidden comment: *)
Capacitor, Ceramic (MLCC), 1.1pF, ±0.1pF, 50V, NP0, ±0.1pF, SMD 0402; Manufacturer: YAGEO; Manufacturer Part Number: CC0402BRNPO9BN1R1
footprint CAP-0402 (0402 (1005M) Capacitor)
pins: 1, 2

## CC0402BRNPO9BN1R2
designator C?  Capacitance: 1.2pF  (hidden comment: *)
Capacitor, Ceramic (MLCC), 1.2pF, ±0.1pF, 50V, NP0, ±0.1pF, SMD 0402; Manufacturer: YAGEO; Manufacturer Part Number: CC0402BRNPO9BN1R2
footprint CAP-0402 (0402 (1005M) Capacitor)
pins: 1, 2

## CC0402BRNPO9BN1R3
designator C?  Capacitance: 1.3pF  (hidden comment: *)
Capacitor, Ceramic (MLCC), 1.3pF, ±0.1pF, 50V, NP0, ±0.1pF, SMD 0402; Manufacturer: YAGEO; Manufacturer Part Number: CC0402BRNPO9BN1R3
footprint CAP-0402 (0402 (1005M) Capacitor)
pins: 1, 2

## CC0402BRNPO9BN1R5
designator C?  Capacitance: 1.5pF  (hidden comment: *)
Capacitor, Ceramic (MLCC), 1.5pF, ±0.1pF, 50V, NP0, ±0.1pF, SMD 0402; Manufacturer: YAGEO; Manufacturer Part Number: CC0402BRNPO9BN1R5
footprint CAP-0402 (0402 (1005M) Capacitor)
pins: 1, 2

## CC0402BRNPO9BN1R6
designator C?  Capacitance: 1.6pF  (hidden comment: *)
Capacitor, Ceramic (MLCC), 1.6pF, ±0.1pF, 50V, NP0, ±0.1pF, SMD 0402; Manufacturer: YAGEO; Manufacturer Part Number: CC0402BRNPO9BN1R6
footprint CAP-0402 (0402 (1005M) Capacitor)
pins: 1, 2

## CC0402BRNPO9BN1R8
designator C?  Capacitance: 1.8pF  (hidden comment: *)
Capacitor, Ceramic (MLCC), 1.8pF, ±0.1pF, 50V, NP0, ±0.1pF, SMD 0402; Manufacturer: YAGEO; Manufacturer Part Number: CC0402BRNPO9BN1R8
footprint CAP-0402 (0402 (1005M) Capacitor)
pins: 1, 2

## CC0402BRNPO9BN2R0
designator C?  Capacitance: 2pF  (hidden comment: *)
Capacitor, Ceramic (MLCC), 2pF, ±0.1pF, 50V, NP0, ±0.1pF, SMD 0402; Manufacturer: YAGEO; Manufacturer Part Number: CC0402BRNPO9BN2R0
footprint CAP-0402 (0402 (1005M) Capacitor)
pins: 1, 2

## CC0402BRNPO9BN2R2
designator C?  Capacitance: 2.2pF  (hidden comment: *)
Capacitor, Ceramic (MLCC), 2.2pF, ±0.1pF, 50V, NP0, ±0.1pF, SMD 0402; Manufacturer: YAGEO; Manufacturer Part Number: CC0402BRNPO9BN2R2
footprint CAP-0402 (0402 (1005M) Capacitor)
pins: 1, 2

## CC0402BRNPO9BN2R4
designator C?  Capacitance: 2.4pF  (hidden comment: *)
Capacitor, Ceramic (MLCC), 2.4pF, ±0.1pF, 50V, NP0, ±0.1pF, SMD 0402; Manufacturer: YAGEO; Manufacturer Part Number: CC0402BRNPO9BN2R4
footprint CAP-0402 (0402 (1005M) Capacitor)
pins: 1, 2

## CC0402BRNPO9BN2R5
designator C?  Capacitance: 2.5pF  (hidden comment: *)
Capacitor, Ceramic (MLCC), 2.5pF, ±0.1pF, 50V, NP0, ±0.1pF, SMD 0402; Manufacturer: YAGEO; Manufacturer Part Number: CC0402BRNPO9BN2R5
footprint CAP-0402 (0402 (1005M) Capacitor)
pins: 1, 2

## CC0402BRNPO9BN2R7
designator C?  Capacitance: 2.7pF  (hidden comment: *)
Capacitor, Ceramic (MLCC), 2.7pF, ±0.1pF, 50V, NP0, ±0.1pF, SMD 0402; Manufacturer: YAGEO; Manufacturer Part Number: CC0402BRNPO9BN2R7
footprint CAP-0402 (0402 (1005M) Capacitor)
pins: 1, 2

## CC0402BRNPO9BN3R0
designator C?  Capacitance: 3pF  (hidden comment: *)
Capacitor, Ceramic (MLCC), 3pF, ±0.1pF, 50V, NP0, ±0.1pF, SMD 0402; Manufacturer: YAGEO; Manufacturer Part Number: CC0402BRNPO9BN3R0
footprint CAP-0402 (0402 (1005M) Capacitor)
pins: 1, 2

## CC0402BRNPO9BN3R3
designator C?  Capacitance: 3.3pF  (hidden comment: *)
Capacitor, Ceramic (MLCC), 3.3pF, ±0.1pF, 50V, NP0, ±0.1pF, SMD 0402; Manufacturer: YAGEO; Manufacturer Part Number: CC0402BRNPO9BN3R3
footprint CAP-0402 (0402 (1005M) Capacitor)
pins: 1, 2

## CC0402BRNPO9BN3R6
designator C?  Capacitance: 3.6pF  (hidden comment: *)
Capacitor, Ceramic (MLCC), 3.6pF, ±0.1pF, 50V, NP0, ±0.1pF, SMD 0402; Manufacturer: YAGEO; Manufacturer Part Number: CC0402BRNPO9BN3R6
footprint CAP-0402 (0402 (1005M) Capacitor)
pins: 1, 2

## CC0402BRNPO9BN3R9
designator C?  Capacitance: 3.9pF  (hidden comment: *)
Capacitor, Ceramic (MLCC), 3.9pF, ±0.1pF, 50V, NP0, ±0.1pF, SMD 0402; Manufacturer: YAGEO; Manufacturer Part Number: CC0402BRNPO9BN3R9
footprint CAP-0402 (0402 (1005M) Capacitor)
pins: 1, 2

## CC0402BRNPO9BN4R0
designator C?  Capacitance: 4pF  (hidden comment: *)
Capacitor, Ceramic (MLCC), 4pF, ±0.1pF, 50V, NP0, ±0.1pF, SMD 0402; Manufacturer: YAGEO; Manufacturer Part Number: CC0402BRNPO9BN4R0
footprint CAP-0402 (0402 (1005M) Capacitor)
pins: 1, 2

## CC0402BRNPO9BN4R3
designator C?  Capacitance: 4.3pF  (hidden comment: *)
Capacitor, Ceramic (MLCC), 4.3pF, ±0.1pF, 50V, NP0, ±0.1pF, SMD 0402; Manufacturer: YAGEO; Manufacturer Part Number: CC0402BRNPO9BN4R3
footprint CAP-0402 (0402 (1005M) Capacitor)
pins: 1, 2

## CC0402BRNPO9BN4R7
designator C?  Capacitance: 4.7pF  (hidden comment: *)
Capacitor, Ceramic (MLCC), 4.7pF, ±0.1pF, 50V, NP0, ±0.1pF, SMD 0402; Manufacturer: YAGEO; Manufacturer Part Number: CC0402BRNPO9BN4R7
footprint CAP-0402 (0402 (1005M) Capacitor)
pins: 1, 2

## CC0402BRNPO9BN5R6
designator C?  Capacitance: 5.6pF  (hidden comment: *)
Capacitor, Ceramic (MLCC), 5.6pF, ±0.1pF, 50V, NP0, ±0.1pF, SMD 0402; Manufacturer: YAGEO; Manufacturer Part Number: CC0402BRNPO9BN5R6
footprint CAP-0402 (0402 (1005M) Capacitor)
pins: 1, 2

## CC0402BRNPO9BN6R8
designator C?  Capacitance: 6.8pF  (hidden comment: *)
Capacitor, Ceramic (MLCC), 6.8pF, ±0.1pF, 50V, NP0, ±0.1pF, SMD 0402; Manufacturer: YAGEO; Manufacturer Part Number: CC0402BRNPO9BN6R8
footprint CAP-0402 (0402 (1005M) Capacitor)
pins: 1, 2

## CC0402BRNPO9BN7R0
designator C?  Capacitance: 7pF  (hidden comment: *)
Capacitor, Ceramic (MLCC), 7pF, ±0.1pF, 50V, NP0, ±0.1pF, SMD 0402; Manufacturer: YAGEO; Manufacturer Part Number: CC0402BRNPO9BN7R0
footprint CAP-0402 (0402 (1005M) Capacitor)
pins: 1, 2

## CC0402BRNPO9BN7R5
designator C?  Capacitance: 7.5pF  (hidden comment: *)
Capacitor, Ceramic (MLCC), 7.5pF, ±0.1pF, 50V, NP0, ±0.1pF, SMD 0402; Manufacturer: YAGEO; Manufacturer Part Number: CC0402BRNPO9BN7R5
footprint CAP-0402 (0402 (1005M) Capacitor)
pins: 1, 2

## CC0402BRNPO9BN8R0
designator C?  Capacitance: 8pF  (hidden comment: *)
Capacitor, Ceramic (MLCC), 8pF, ±0.1pF, 50V, NP0, ±0.1pF, SMD 0402; Manufacturer: YAGEO; Manufacturer Part Number: CC0402BRNPO9BN8R0
footprint CAP-0402 (0402 (1005M) Capacitor)
pins: 1, 2

## CC0402BRNPO9BN8R2
designator C?  Capacitance: 8.2pF  (hidden comment: *)
Capacitor, Ceramic (MLCC), 8.2pF, ±0.1pF, 50V, NP0, ±0.1pF, SMD 0402; Manufacturer: YAGEO; Manufacturer Part Number: CC0402BRNPO9BN8R2
footprint CAP-0402 (0402 (1005M) Capacitor)
pins: 1, 2

## CC0402BRNPO9BN9R0
designator C?  Capacitance: 9pF  (hidden comment: *)
Capacitor, Ceramic (MLCC), 9pF, ±0.1pF, 50V, NP0, ±0.1pF, SMD 0402; Manufacturer: YAGEO; Manufacturer Part Number: CC0402BRNPO9BN9R0
footprint CAP-0402 (0402 (1005M) Capacitor)
pins: 1, 2

## CC0402BRNPO9BNR47
designator C?  Capacitance: 0.47pF  (hidden comment: *)
Capacitor, Ceramic (MLCC), 0.47pF, ±0.1pF, 50V, NP0, ±0.1pF, SMD 0402; Manufacturer: YAGEO; Manufacturer Part Number: CC0402BRNPO9BNR47
footprint CAP-0402 (0402 (1005M) Capacitor)
pins: 1, 2

## CC0402BRNPO9BNR50
designator C?  Capacitance: 0.5pF  (hidden comment: *)
Capacitor, Ceramic (MLCC), 0.5pF, ±0.1pF, 50V, NP0, ±0.1pF, SMD 0402; Manufacturer: YAGEO; Manufacturer Part Number: CC0402BRNPO9BNR50
footprint CAP-0402 (0402 (1005M) Capacitor)
pins: 1, 2

## CC0402BRNPO9BNR60
designator C?  Capacitance: 0.6pF  (hidden comment: *)
Capacitor, Ceramic (MLCC), 0.6pF, ±0.1pF, 50V, NP0, ±0.1pF, SMD 0402; Manufacturer: YAGEO; Manufacturer Part Number: CC0402BRNPO9BNR60
footprint CAP-0402 (0402 (1005M) Capacitor)
pins: 1, 2

## CC0402BRNPO9BNR68
designator C?  Capacitance: 0.68pF  (hidden comment: *)
Capacitor, Ceramic (MLCC), 0.68pF, ±0.1pF, 50V, NP0, ±0.1pF, SMD 0402; Manufacturer: YAGEO; Manufacturer Part Number: CC0402BRNPO9BNR68
footprint CAP-0402 (0402 (1005M) Capacitor)
pins: 1, 2

## CC0402BRNPO9BNR70
designator C?  Capacitance: 0.7pF  (hidden comment: *)
Capacitor, Ceramic (MLCC), 0.7pF, ±0.1pF, 50V, NP0, ±0.1pF, SMD 0402; Manufacturer: YAGEO; Manufacturer Part Number: CC0402BRNPO9BNR70
footprint CAP-0402 (0402 (1005M) Capacitor)
pins: 1, 2

## CC0402BRNPO9BNR75
designator C?  Capacitance: 0.75pF  (hidden comment: *)
Capacitor, Ceramic (MLCC), 0.75pF, ±0.1pF, 50V, NP0, ±0.1pF, SMD 0402; Manufacturer: YAGEO; Manufacturer Part Number: CC0402BRNPO9BNR75
footprint CAP-0402 (0402 (1005M) Capacitor)
pins: 1, 2

## CC0402BRNPO9BNR80
designator C?  Capacitance: 0.8pF  (hidden comment: *)
Capacitor, Ceramic (MLCC), 0.8pF, ±0.1pF, 50V, NP0, ±0.1pF, SMD 0402; Manufacturer: YAGEO; Manufacturer Part Number: CC0402BRNPO9BNR80
footprint CAP-0402 (0402 (1005M) Capacitor)
pins: 1, 2

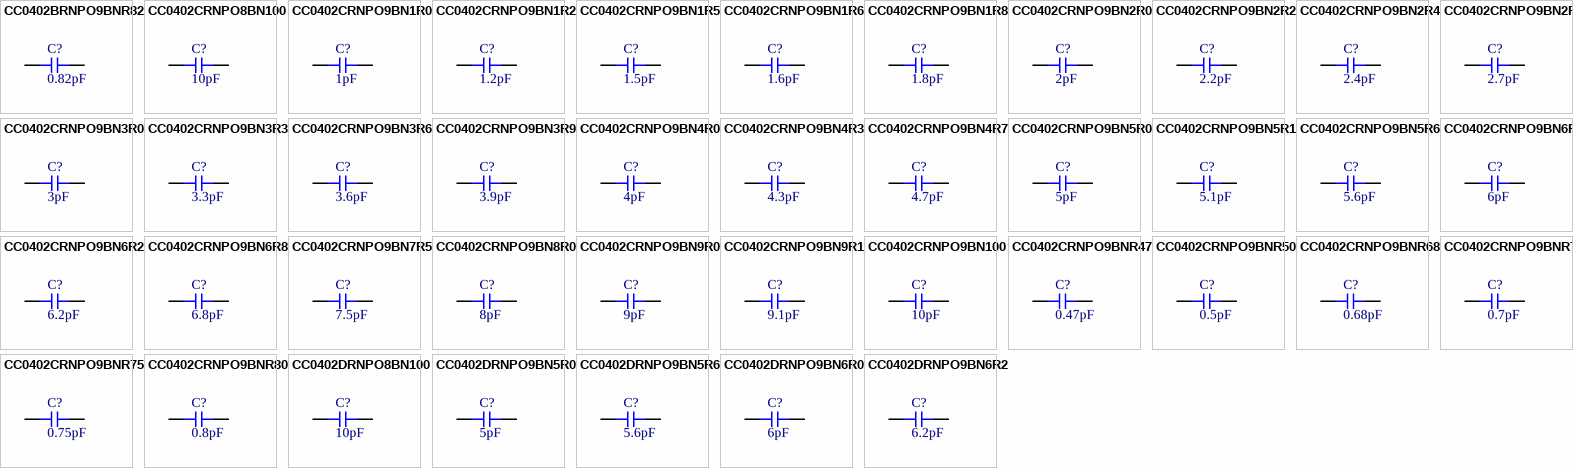
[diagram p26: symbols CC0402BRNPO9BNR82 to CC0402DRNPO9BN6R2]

## CC0402BRNPO9BNR82
designator C?  Capacitance: 0.82pF  (hidden comment: *)
Capacitor, Ceramic (MLCC), 0.82pF, ±0.1pF, 50V, NP0, ±0.1pF, SMD 0402; Manufacturer: YAGEO; Manufacturer Part Number: CC0402BRNPO9BNR82
footprint CAP-0402 (0402 (1005M) Capacitor)
pins: 1, 2

## CC0402CRNPO8BN100
designator C?  Capacitance: 10pF  (hidden comment: *)
Capacitor, Ceramic (MLCC), 10pF, ±0.25pF, 25V, NP0, ±0.25pF, SMD 0402; Manufacturer: YAGEO; Manufacturer Part Number: CC0402CRNPO8BN100
footprint CAP-0402 (0402 (1005M) Capacitor)
pins: 1, 2

## CC0402CRNPO9BN1R0
designator C?  Capacitance: 1pF  (hidden comment: *)
Capacitor, Ceramic (MLCC), 1pF, ±0.25pF, 50V, NP0, ±0.25pF, SMD 0402; Manufacturer: YAGEO; Manufacturer Part Number: CC0402CRNPO9BN1R0
footprint CAP-0402 (0402 (1005M) Capacitor)
pins: 1, 2

## CC0402CRNPO9BN1R2
designator C?  Capacitance: 1.2pF  (hidden comment: *)
Capacitor, Ceramic (MLCC), 1.2pF, ±0.25pF, 50V, NP0, ±0.25pF, SMD 0402; Manufacturer: YAGEO; Manufacturer Part Number: CC0402CRNPO9BN1R2
footprint CAP-0402 (0402 (1005M) Capacitor)
pins: 1, 2

## CC0402CRNPO9BN1R5
designator C?  Capacitance: 1.5pF  (hidden comment: *)
Capacitor, Ceramic (MLCC), 1.5pF, ±0.25pF, 50V, NP0, ±0.25pF, SMD 0402; Manufacturer: YAGEO; Manufacturer Part Number: CC0402CRNPO9BN1R5
footprint CAP-0402 (0402 (1005M) Capacitor)
pins: 1, 2

## CC0402CRNPO9BN1R6
designator C?  Capacitance: 1.6pF  (hidden comment: *)
Capacitor, Ceramic (MLCC), 1.6pF, ±0.25pF, 50V, NP0, ±0.25pF, SMD 0402; Manufacturer: YAGEO; Manufacturer Part Number: CC0402CRNPO9BN1R6
footprint CAP-0402 (0402 (1005M) Capacitor)
pins: 1, 2

## CC0402CRNPO9BN1R8
designator C?  Capacitance: 1.8pF  (hidden comment: *)
Capacitor, Ceramic (MLCC), 1.8pF, ±0.25pF, 50V, NP0, ±0.25pF, SMD 0402; Manufacturer: YAGEO; Manufacturer Part Number: CC0402CRNPO9BN1R8
footprint CAP-0402 (0402 (1005M) Capacitor)
pins: 1, 2

## CC0402CRNPO9BN2R0
designator C?  Capacitance: 2pF  (hidden comment: *)
Capacitor, Ceramic (MLCC), 2pF, ±0.25pF, 50V, NP0, ±0.25pF, SMD 0402; Manufacturer: YAGEO; Manufacturer Part Number: CC0402CRNPO9BN2R0
footprint CAP-0402 (0402 (1005M) Capacitor)
pins: 1, 2

## CC0402CRNPO9BN2R2
designator C?  Capacitance: 2.2pF  (hidden comment: *)
Capacitor, Ceramic (MLCC), 2.2pF, ±0.25pF, 50V, NP0, ±0.25pF, SMD 0402; Manufacturer: YAGEO; Manufacturer Part Number: CC0402CRNPO9BN2R2
footprint CAP-0402 (0402 (1005M) Capacitor)
pins: 1, 2

## CC0402CRNPO9BN2R4
designator C?  Capacitance: 2.4pF  (hidden comment: *)
Capacitor, Ceramic (MLCC), 2.4pF, ±0.25pF, 50V, NP0, ±0.25pF, SMD 0402; Manufacturer: YAGEO; Manufacturer Part Number: CC0402CRNPO9BN2R4
footprint CAP-0402 (0402 (1005M) Capacitor)
pins: 1, 2

## CC0402CRNPO9BN2R7
designator C?  Capacitance: 2.7pF  (hidden comment: *)
Capacitor, Ceramic (MLCC), 2.7pF, ±0.25pF, 50V, NP0, ±0.25pF, SMD 0402; Manufacturer: YAGEO; Manufacturer Part Number: CC0402CRNPO9BN2R7
footprint CAP-0402 (0402 (1005M) Capacitor)
pins: 1, 2

## CC0402CRNPO9BN3R0
designator C?  Capacitance: 3pF  (hidden comment: *)
Capacitor, Ceramic (MLCC), 3pF, ±0.25pF, 50V, NP0, ±0.25pF, SMD 0402; Manufacturer: YAGEO; Manufacturer Part Number: CC0402CRNPO9BN3R0
footprint CAP-0402 (0402 (1005M) Capacitor)
pins: 1, 2

## CC0402CRNPO9BN3R3
designator C?  Capacitance: 3.3pF  (hidden comment: *)
Capacitor, Ceramic (MLCC), 3.3pF, ±0.25pF, 50V, NP0, ±0.25pF, SMD 0402; Manufacturer: YAGEO; Manufacturer Part Number: CC0402CRNPO9BN3R3
footprint CAP-0402 (0402 (1005M) Capacitor)
pins: 1, 2

## CC0402CRNPO9BN3R6
designator C?  Capacitance: 3.6pF  (hidden comment: *)
Capacitor, Ceramic (MLCC), 3.6pF, ±0.25pF, 50V, NP0, ±0.25pF, SMD 0402; Manufacturer: YAGEO; Manufacturer Part Number: CC0402CRNPO9BN3R6
footprint CAP-0402 (0402 (1005M) Capacitor)
pins: 1, 2

## CC0402CRNPO9BN3R9
designator C?  Capacitance: 3.9pF  (hidden comment: *)
Capacitor, Ceramic (MLCC), 3.9pF, ±0.25pF, 50V, NP0, ±0.25pF, SMD 0402; Manufacturer: YAGEO; Manufacturer Part Number: CC0402CRNPO9BN3R9
footprint CAP-0402 (0402 (1005M) Capacitor)
pins: 1, 2

## CC0402CRNPO9BN4R0
designator C?  Capacitance: 4pF  (hidden comment: *)
Capacitor, Ceramic (MLCC), 4pF, ±0.25pF, 50V, NP0, ±0.25pF, SMD 0402; Manufacturer: YAGEO; Manufacturer Part Number: CC0402CRNPO9BN4R0
footprint CAP-0402 (0402 (1005M) Capacitor)
pins: 1, 2

## CC0402CRNPO9BN4R3
designator C?  Capacitance: 4.3pF  (hidden comment: *)
Capacitor, Ceramic (MLCC), 4.3pF, ±0.25pF, 50V, NP0, ±0.25pF, SMD 0402; Manufacturer: YAGEO; Manufacturer Part Number: CC0402CRNPO9BN4R3
footprint CAP-0402 (0402 (1005M) Capacitor)
pins: 1, 2

## CC0402CRNPO9BN4R7
designator C?  Capacitance: 4.7pF  (hidden comment: *)
Capacitor, Ceramic (MLCC), 4.7pF, ±0.25pF, 50V, NP0, ±0.25pF, SMD 0402; Manufacturer: YAGEO; Manufacturer Part Number: CC0402CRNPO9BN4R7
footprint CAP-0402 (0402 (1005M) Capacitor)
pins: 1, 2

## CC0402CRNPO9BN5R0
designator C?  Capacitance: 5pF  (hidden comment: *)
Capacitor, Ceramic (MLCC), 5pF, ±0.25pF, 50V, NP0, ±0.25pF, SMD 0402; Manufacturer: YAGEO; Manufacturer Part Number: CC0402CRNPO9BN5R0
footprint CAP-0402 (0402 (1005M) Capacitor)
pins: 1, 2

## CC0402CRNPO9BN5R1
designator C?  Capacitance: 5.1pF  (hidden comment: *)
Capacitor, Ceramic (MLCC), 5.1pF, ±0.25pF, 50V, NP0, ±0.25pF, SMD 0402; Manufacturer: YAGEO; Manufacturer Part Number: CC0402CRNPO9BN5R1
footprint CAP-0402 (0402 (1005M) Capacitor)
pins: 1, 2

## CC0402CRNPO9BN5R6
designator C?  Capacitance: 5.6pF  (hidden comment: *)
Capacitor, Ceramic (MLCC), 5.6pF, ±0.25pF, 50V, NP0, ±0.25pF, SMD 0402; Manufacturer: YAGEO; Manufacturer Part Number: CC0402CRNPO9BN5R6
footprint CAP-0402 (0402 (1005M) Capacitor)
pins: 1, 2

## CC0402CRNPO9BN6R0
designator C?  Capacitance: 6pF  (hidden comment: *)
Capacitor, Ceramic (MLCC), 6pF, ±0.25pF, 50V, NP0, ±0.25pF, SMD 0402; Manufacturer: YAGEO; Manufacturer Part Number: CC0402CRNPO9BN6R0
footprint CAP-0402 (0402 (1005M) Capacitor)
pins: 1, 2

## CC0402CRNPO9BN6R2
designator C?  Capacitance: 6.2pF  (hidden comment: *)
Capacitor, Ceramic (MLCC), 6.2pF, ±0.25pF, 50V, NP0, ±0.25pF, SMD 0402; Manufacturer: YAGEO; Manufacturer Part Number: CC0402CRNPO9BN6R2
footprint CAP-0402 (0402 (1005M) Capacitor)
pins: 1, 2

## CC0402CRNPO9BN6R8
designator C?  Capacitance: 6.8pF  (hidden comment: *)
Capacitor, Ceramic (MLCC), 6.8pF, ±0.25pF, 50V, NP0, ±0.25pF, SMD 0402; Manufacturer: YAGEO; Manufacturer Part Number: CC0402CRNPO9BN6R8
footprint CAP-0402 (0402 (1005M) Capacitor)
pins: 1, 2

## CC0402CRNPO9BN7R5
designator C?  Capacitance: 7.5pF  (hidden comment: *)
Capacitor, Ceramic (MLCC), 7.5pF, ±0.25pF, 50V, NP0, ±0.25pF, SMD 0402; Manufacturer: YAGEO; Manufacturer Part Number: CC0402CRNPO9BN7R5
footprint CAP-0402 (0402 (1005M) Capacitor)
pins: 1, 2

## CC0402CRNPO9BN8R0
designator C?  Capacitance: 8pF  (hidden comment: *)
Capacitor, Ceramic (MLCC), 8pF, ±0.25pF, 50V, NP0, ±0.25pF, SMD 0402; Manufacturer: YAGEO; Manufacturer Part Number: CC0402CRNPO9BN8R0
footprint CAP-0402 (0402 (1005M) Capacitor)
pins: 1, 2

## CC0402CRNPO9BN9R0
designator C?  Capacitance: 9pF  (hidden comment: *)
Capacitor, Ceramic (MLCC), 9pF, ±0.25pF, 50V, NP0, ±0.25pF, SMD 0402; Manufacturer: YAGEO; Manufacturer Part Number: CC0402CRNPO9BN9R0
footprint CAP-0402 (0402 (1005M) Capacitor)
pins: 1, 2

## CC0402CRNPO9BN9R1
designator C?  Capacitance: 9.1pF  (hidden comment: *)
Capacitor, Ceramic (MLCC), 9.1pF, ±0.25pF, 50V, NP0, ±0.25pF, SMD 0402; Manufacturer: YAGEO; Manufacturer Part Number: CC0402CRNPO9BN9R1
footprint CAP-0402 (0402 (1005M) Capacitor)
pins: 1, 2

## CC0402CRNPO9BN100
designator C?  Capacitance: 10pF  (hidden comment: *)
Capacitor, Ceramic (MLCC), 10pF, ±0.25pF, 50V, NP0, ±0.25pF, SMD 0402; Manufacturer: YAGEO; Manufacturer Part Number: CC0402CRNPO9BN100
footprint CAP-0402 (0402 (1005M) Capacitor)
pins: 1, 2

## CC0402CRNPO9BNR47
designator C?  Capacitance: 0.47pF  (hidden comment: *)
Capacitor, Ceramic (MLCC), 0.47pF, ±0.25pF, 50V, NP0, ±0.25pF, SMD 0402; Manufacturer: YAGEO; Manufacturer Part Number: CC0402CRNPO9BNR47
footprint CAP-0402 (0402 (1005M) Capacitor)
pins: 1, 2

## CC0402CRNPO9BNR50
designator C?  Capacitance: 0.5pF  (hidden comment: *)
Capacitor, Ceramic (MLCC), 0.5pF, ±0.25pF, 50V, NP0, ±0.25pF, SMD 0402; Manufacturer: YAGEO; Manufacturer Part Number: CC0402CRNPO9BNR50
footprint CAP-0402 (0402 (1005M) Capacitor)
pins: 1, 2

## CC0402CRNPO9BNR68
designator C?  Capacitance: 0.68pF  (hidden comment: *)
Capacitor, Ceramic (MLCC), 0.68pF, ±0.25pF, 50V, NP0, ±0.25pF, SMD 0402; Manufacturer: YAGEO; Manufacturer Part Number: CC0402CRNPO9BNR68
footprint CAP-0402 (0402 (1005M) Capacitor)
pins: 1, 2

## CC0402CRNPO9BNR70
designator C?  Capacitance: 0.7pF  (hidden comment: *)
Capacitor, Ceramic (MLCC), 0.7pF, ±0.25pF, 50V, NP0, ±0.25pF, SMD 0402; Manufacturer: YAGEO; Manufacturer Part Number: CC0402CRNPO9BNR70
footprint CAP-0402 (0402 (1005M) Capacitor)
pins: 1, 2

## CC0402CRNPO9BNR75
designator C?  Capacitance: 0.75pF  (hidden comment: *)
Capacitor, Ceramic (MLCC), 0.75pF, ±0.25pF, 50V, NP0, ±0.25pF, SMD 0402; Manufacturer: YAGEO; Manufacturer Part Number: CC0402CRNPO9BNR75
footprint CAP-0402 (0402 (1005M) Capacitor)
pins: 1, 2

## CC0402CRNPO9BNR80
designator C?  Capacitance: 0.8pF  (hidden comment: *)
Capacitor, Ceramic (MLCC), 0.8pF, ±0.25pF, 50V, NP0, ±0.25pF, SMD 0402; Manufacturer: YAGEO; Manufacturer Part Number: CC0402CRNPO9BNR80
footprint CAP-0402 (0402 (1005M) Capacitor)
pins: 1, 2

## CC0402DRNPO8BN100
designator C?  Capacitance: 10pF  (hidden comment: *)
Capacitor, Ceramic (MLCC), 10pF, ±0.5pF, 25V, NP0, ±0.5pF, SMD 0402; Manufacturer: YAGEO; Manufacturer Part Number: CC0402DRNPO8BN100
footprint CAP-0402 (0402 (1005M) Capacitor)
pins: 1, 2

## CC0402DRNPO9BN5R0
designator C?  Capacitance: 5pF  (hidden comment: *)
Capacitor, Ceramic (MLCC), 5pF, ±0.5pF, 50V, NP0, ±0.5pF, SMD 0402; Manufacturer: YAGEO; Manufacturer Part Number: CC0402DRNPO9BN5R0
footprint CAP-0402 (0402 (1005M) Capacitor)
pins: 1, 2

## CC0402DRNPO9BN5R6
designator C?  Capacitance: 5.6pF  (hidden comment: *)
Capacitor, Ceramic (MLCC), 5.6pF, ±0.5pF, 50V, NP0, ±0.5pF, SMD 0402; Manufacturer: YAGEO; Manufacturer Part Number: CC0402DRNPO9BN5R6
footprint CAP-0402 (0402 (1005M) Capacitor)
pins: 1, 2

## CC0402DRNPO9BN6R0
designator C?  Capacitance: 6pF  (hidden comment: *)
Capacitor, Ceramic (MLCC), 6pF, ±0.5pF, 50V, NP0, ±0.5pF, SMD 0402; Manufacturer: YAGEO; Manufacturer Part Number: CC0402DRNPO9BN6R0
footprint CAP-0402 (0402 (1005M) Capacitor)
pins: 1, 2

## CC0402DRNPO9BN6R2
designator C?  Capacitance: 6.2pF  (hidden comment: *)
Capacitor, Ceramic (MLCC), 6.2pF, ±0.5pF, 50V, NP0, ±0.5pF, SMD 0402; Manufacturer: YAGEO; Manufacturer Part Number: CC0402DRNPO9BN6R2
footprint CAP-0402 (0402 (1005M) Capacitor)
pins: 1, 2

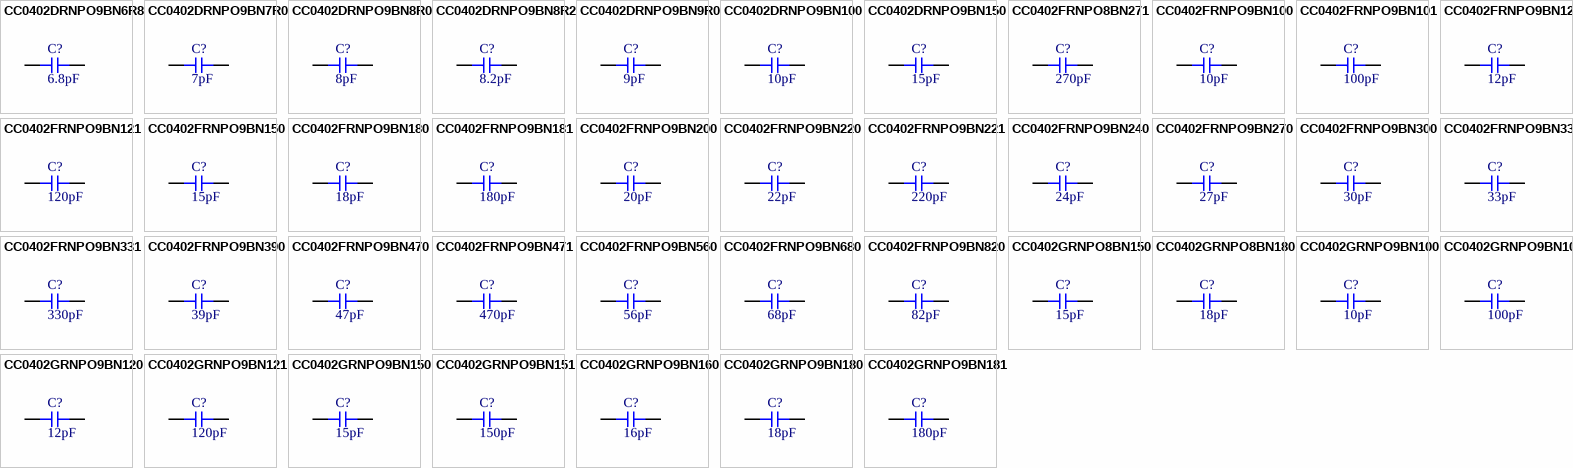
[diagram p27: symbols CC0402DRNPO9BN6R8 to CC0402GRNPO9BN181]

## CC0402DRNPO9BN6R8
designator C?  Capacitance: 6.8pF  (hidden comment: *)
Capacitor, Ceramic (MLCC), 6.8pF, ±0.5pF, 50V, NP0, ±0.5pF, SMD 0402; Manufacturer: YAGEO; Manufacturer Part Number: CC0402DRNPO9BN6R8
footprint CAP-0402 (0402 (1005M) Capacitor)
pins: 1, 2

## CC0402DRNPO9BN7R0
designator C?  Capacitance: 7pF  (hidden comment: *)
Capacitor, Ceramic (MLCC), 7pF, ±0.5pF, 50V, NP0, ±0.5pF, SMD 0402; Manufacturer: YAGEO; Manufacturer Part Number: CC0402DRNPO9BN7R0
footprint CAP-0402 (0402 (1005M) Capacitor)
pins: 1, 2

## CC0402DRNPO9BN8R0
designator C?  Capacitance: 8pF  (hidden comment: *)
Capacitor, Ceramic (MLCC), 8pF, ±0.5pF, 50V, NP0, ±0.5pF, SMD 0402; Manufacturer: YAGEO; Manufacturer Part Number: CC0402DRNPO9BN8R0
footprint CAP-0402 (0402 (1005M) Capacitor)
pins: 1, 2

## CC0402DRNPO9BN8R2
designator C?  Capacitance: 8.2pF  (hidden comment: *)
Capacitor, Ceramic (MLCC), 8.2pF, ±0.5pF, 50V, NP0, ±0.5pF, SMD 0402; Manufacturer: YAGEO; Manufacturer Part Number: CC0402DRNPO9BN8R2
footprint CAP-0402 (0402 (1005M) Capacitor)
pins: 1, 2

## CC0402DRNPO9BN9R0
designator C?  Capacitance: 9pF  (hidden comment: *)
Capacitor, Ceramic (MLCC), 9pF, ±0.5pF, 50V, NP0, ±0.5pF, SMD 0402; Manufacturer: YAGEO; Manufacturer Part Number: CC0402DRNPO9BN9R0
footprint CAP-0402 (0402 (1005M) Capacitor)
pins: 1, 2

## CC0402DRNPO9BN100
designator C?  Capacitance: 10pF  (hidden comment: *)
Capacitor, Ceramic (MLCC), 10pF, ±0.5pF, 50V, NP0, ±0.5pF, SMD 0402; Manufacturer: YAGEO; Manufacturer Part Number: CC0402DRNPO9BN100
footprint CAP-0402 (0402 (1005M) Capacitor)
pins: 1, 2

## CC0402DRNPO9BN150
designator C?  Capacitance: 15pF  (hidden comment: *)
Capacitor, Ceramic (MLCC), 15pF, ±0.5pF, 50V, NP0, ±0.5pF, SMD 0402; Manufacturer: YAGEO; Manufacturer Part Number: CC0402DRNPO9BN150
footprint CAP-0402 (0402 (1005M) Capacitor)
pins: 1, 2

## CC0402FRNPO8BN271
designator C?  Capacitance: 270pF  (hidden comment: *)
Capacitor, Ceramic (MLCC), 270pF, ±1%, 25V, NP0, ±1%, SMD 0402; Manufacturer: YAGEO; Manufacturer Part Number: CC0402FRNPO8BN271
footprint CAP-0402 (0402 (1005M) Capacitor)
pins: 1, 2

## CC0402FRNPO9BN100
designator C?  Capacitance: 10pF  (hidden comment: *)
Capacitor, Ceramic (MLCC), 10pF, ±1%, 50V, NP0, ±1%, SMD 0402; Manufacturer: YAGEO; Manufacturer Part Number: CC0402FRNPO9BN100
footprint CAP-0402 (0402 (1005M) Capacitor)
pins: 1, 2

## CC0402FRNPO9BN101
designator C?  Capacitance: 100pF  (hidden comment: *)
Capacitor, Ceramic (MLCC), 100pF, ±1%, 50V, NP0, ±1%, SMD 0402; Manufacturer: YAGEO; Manufacturer Part Number: CC0402FRNPO9BN101
footprint CAP-0402 (0402 (1005M) Capacitor)
pins: 1, 2

## CC0402FRNPO9BN120
designator C?  Capacitance: 12pF  (hidden comment: *)
Capacitor, Ceramic (MLCC), 12pF, ±1%, 50V, NP0, ±1%, SMD 0402; Manufacturer: YAGEO; Manufacturer Part Number: CC0402FRNPO9BN120
footprint CAP-0402 (0402 (1005M) Capacitor)
pins: 1, 2

## CC0402FRNPO9BN121
designator C?  Capacitance: 120pF  (hidden comment: *)
Capacitor, Ceramic (MLCC), 120pF, ±1pF, 50V, NP0, ±1pF, SMD 0402; Manufacturer: YAGEO; Manufacturer Part Number: CC0402FRNPO9BN121
footprint CAP-0402 (0402 (1005M) Capacitor)
pins: 1, 2

## CC0402FRNPO9BN150
designator C?  Capacitance: 15pF  (hidden comment: *)
Capacitor, Ceramic (MLCC), 15pF, ±1%, 50V, NP0, ±1%, SMD 0402; Manufacturer: YAGEO; Manufacturer Part Number: CC0402FRNPO9BN150
footprint CAP-0402 (0402 (1005M) Capacitor)
pins: 1, 2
